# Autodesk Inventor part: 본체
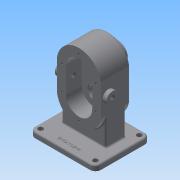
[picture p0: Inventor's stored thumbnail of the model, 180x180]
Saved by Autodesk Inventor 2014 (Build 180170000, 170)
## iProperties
Created: 2020-09
Part Number: 본체
Material: 일반
Document SubType Name: Modeling
Designer: NET
Density: 1 g/cm^3
Appearance: 기본값
Author: NET
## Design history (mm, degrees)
sketch "스케치1"
  geometry: L1 (40, 0)-(-40, 0); L2 (40, 0)-(40, 29.174); L3 (-40, 29.174)-(-40, 0); L4 (-40, -29.174)-(-40, 0); L5 (40, 0)-(40, -29.174); A1 r 40.638 centre (0, 22) between (40, 29.174) and (-40, 29.174); A2 r 40.638 centre (0, -22) between (-40, -29.174) and (40, -29.174); 2 further points
  constraints: 10 end point, 4 point on circle, 3 symmetric about line, 2 centre point, 1 coincident, 1 horizontal, 1 midpoint, 1 parallel, 1 perpendicular, 1 other
  dimensions: "d0" = 80 distance of L1.start L1.end; "d104" = 44 distance of A2.centre A1.centre
extrude "돌출1" new body sketch "스케치1" distance "d1" = 53; taper "d2" = 0 deg
node "작업 평면1"
sketch "스케치2"
  geometry: L1 (40, 53)-(-40, 53) reference; L2 (-40, 0)-(-40, 53) reference; L3 (40, 0)-(-40, 0) reference; L4 (40, -30)-(-40, -30); L5 (-40, 70)-(40, 70); L6 (40, 70)-(40, 70); L7 (-40, 26.5)-(40, 26.5); L8 (-40, 70)-(-60, 70); L9 (-60, 70)-(-60, -30); L10 (-60, -30)-(-40, -30); L11 (40, 70)-(60, 70); L12 (60, 70)-(60, -30); L13 (60, -30)-(40, -30); 2 further points
  constraints: 21 end point, 4 parallel, 2 perpendicular, 1 point on line
extrude "돌출2" join sketch "스케치2" distance "d8" = 10; taper "d9" = 0 deg
sketch "스케치3"
  geometry: L1 (-40, 70)-(-40, -30) reference; L2 (40, -30)-(40, 70) reference; L3 (60, 70)-(-60, 70) reference; L4 (-40, 45)-(40, 45); L5 (40, 45)-(40, 8); L6 (40, 8)-(-40, 8); L7 (-40, 8)-(-40, 45); 1 further point
  constraints: 8 end point, 2 parallel, 2 point on line, 1 horizontal, 1 perpendicular
  dimensions: "d10" = 25 distance between parallel lines of L4 L3; "d11" = 37 distance between parallel lines of L6 L4
extrude "돌출3" join sketch "스케치3" stored distance "d12" = 10; taper "d13" = 0 deg
sketch "스케치4"
  geometry: L1 (-24, 22)-(-24, -22); L2 (24, -22)-(24, 22); A1 r 40.638 centre (0, -22) between (-40, -29.174) and (40, -29.174) reference; A2 r 40.638 centre (0, 22) between (40, 29.174) and (-40, 29.174) reference; A3 r 24 centre (0, 22) between (24, 22) and (-24, 22); A4 r 24 centre (0, -22) between (-24, -22) and (24, -22); 1 further point
  constraints: 4 end point, 4 point on circle, 3 tangent, 2 centre point, 2 coincident
  dimensions: "d14" = 48 diameter of A3; "d15" = 48 diameter of A4
extrude "돌출4" cut sketch "스케치4" distance "d16" = 29; taper "d17" = 0 deg
sketch "스케치5"
  geometry: C1 r 12.5 at (0, 22); C2 r 12.5 at (0, -22); A1 r 24 centre (0, 22) between (24, 22) and (-24, 22) reference; A2 r 24 centre (0, -22) between (-24, -22) and (24, -22) reference; 1 further point
  constraints: 2 centre point, 2 coincident
  dimensions: "d18" = 25 diameter of C1; "d19" = 25 diameter of C2
extrude "돌출5" cut sketch "스케치5" distance "d20" = 15; taper "d21" = 0 deg
sketch "스케치6"
  geometry: C1 r 19 at (0, -22); A1 r 40.638 centre (0, -22) between (-40, -29.174) and (40, -29.174) reference; 1 further point
  constraints: 1 centre point, 1 coincident
  dimensions: "d22" = 38 diameter of C1
extrude "돌출6" join sketch "스케치6" distance "d23" = 17; taper "d24" = 0 deg
sketch "스케치7"
  geometry: C1 r 19 at (0, 0) reference; C2 r 14 at (0, 0); 1 further point
  constraints: 1 centre point, 1 coincident
  dimensions: "d25" = 28 diameter of C2
extrude "돌출7" cut sketch "스케치7" distance "d26" = 7.3; taper "d27" = 0 deg
sketch "스케치8"
  geometry: C1 r 14 at (0, 0) reference; C2 r 8.5 at (0, 0); 1 further point
  constraints: 1 centre point, 1 coincident
  dimensions: "d28" = 17 diameter of C2
extrude "돌출8" cut sketch "스케치8" stored distance "d29" = 7.3; taper "d30" = 0 deg
chamfer "모따기1" distance "d31" = 1; stored, may be unused: second distance "d32" = 2, angle "d33" = 45 deg
sketch "스케치10"
  geometry: L1 (45, -62.638)-(45, -80) reference; L2 (45, -80)-(70, -80) reference; L3 (70, -80)-(70, -90) reference; L4 (70, -90)-(-30, -90) reference; L5 (-30, -90)-(-30, -80) reference; L6 (-30, -80)-(8, -80) reference; L7 (8, -80)-(8, -62.638) reference; L8 (8, -62.638)-(0, -62.638) reference; L9 (0, -62.638)-(0, -46) reference; L10 (0, -46)-(29, -46) reference; L11 (29, -46)-(29, -35.5) reference; L12 (29, -35.5)-(30, -34.5) reference; L13 (30, -34.5)-(44, -34.5) reference; L14 (44, -34.5)-(44, -9.5) reference; L15 (44, -9.5)-(30, -9.5) reference; L16 (30, -9.5)-(29, -8.5) reference; L17 (29, -8.5)-(29, 8.5) reference; L18 (29, 8.5)-(30, 9.5) reference; L19 (30, 9.5)-(44, 9.5) reference; L20 (44, 9.5)-(44, 13.5) reference; L21 (44, 13.5)-(62.7, 13.5) reference; L22 (62.7, 13.5)-(62.7, 8) reference; L23 (62.7, 8)-(70, 8) reference; L24 (70, 8)-(70, 3) reference; L25 (70, 3)-(53, 3) reference; L26 (53, 3)-(53, -62.638) reference; L27 (53, -62.638)-(45, -62.638) reference; L28 (0, 62.638)-(53, 62.638) reference; L29 (53, 62.638)-(53, 41) reference; L30 (53, 41)-(70, 41) reference; L31 (70, 41)-(70, 36) reference; L32 (70, 36)-(62.7, 36) reference; L33 (62.7, 36)-(62.7, 30.5) reference; L34 (62.7, 30.5)-(44, 30.5) reference; L35 (44, 30.5)-(44, 34.5) reference; L36 (44, 34.5)-(30, 34.5) reference; L37 (30, 34.5)-(29, 35.5) reference; L38 (29, 35.5)-(29, 46) reference; L39 (29, 46)-(0, 46) reference; L40 (0, 46)-(0, 62.638) reference; L41 (69.3, 36)-(70, 36.404); 1 further point
  constraints: 2 end point, 2 point on line
  dimensions: "d34" = 30 deg angle of L32 L41; "d35" = 0.7 distance from line of L31 L41.start
  node "절단 모서리 투영1"
fillet "모깎기1" dims "d36" = 0.5
sketch "스케치14"
  geometry: L1 (-31, 22)-(31, -22); L2 (31, 22)-(-31, -22); 5 further points
  constraints: 4 coincident, 4 end point, 2 midpoint
hole "구멍2" sketch "스케치14" diameter "d56" = 4.134; stored, may be unused: countersink angle "d60" = 90 deg, drill point angle "d62" = 118 deg; dims "d57" = 10, "d58" = 4, "d59" = 2, "d61" = 12
sketch "스케치16"
  geometry: L1 (0, 0)-(58.348, 0) reference; L2 (119.174, -20)-(119.174, 60) reference; C1 r 11 at (29.174, 14); 2 further points
  constraints: 1 centre point, 1 coincident
  dimensions: "d70" = 90 distance from line of L2 point (29.174, 14); "d71" = 14 distance from line of L1 point (29.174, 14); "d72" = 22 diameter of C1
extrude "돌출11" join sketch "스케치16" distance "d73" = 7.1; taper "d74" = 0 deg
sketch "스케치17"
  geometry: C1 r 11 at (0, 0) reference; 2 further points
  constraints: 1 coincident
hole "구멍4" sketch "스케치17" at (0, 0) diameter "d75" = 8.376; stored, may be unused: countersink angle "d79" = 90 deg, drill point angle "d81" = 118 deg; dims "d76" = 10, "d77" = 4, "d78" = 2, "d80" = 30
fillet "모깎기3" dims "d85" = 10
sketch "스케치18"
  geometry: C1 r 4.5 at (50, -20); C2 r 4.5 at (50, 60); C3 r 4.5 at (-50, 60); C4 r 4.5 at (-50, -20); A1 r 10 centre (-50, 60) between (-50, 70) and (-60, 60) reference; A2 r 10 centre (-50, -20) between (-60, -20) and (-50, -30) reference; A3 r 10 centre (50, -20) between (50, -30) and (60, -20) reference; A4 r 10 centre (50, 60) between (60, 60) and (50, 70) reference; 1 further point
  constraints: 4 centre point, 4 coincident
  dimensions: "d87" = 9 diameter of C1; "d88" = 9 diameter of C2; "d89" = 9 diameter of C3; "d90" = 9 diameter of C4
extrude "돌출12" cut sketch "스케치18" stored distance "d91" = 7.1; taper "d92" = 0 deg
node "작업 평면2"
sketch "스케치19"
  geometry: L1 (50, -30)-(-50, -30) reference; L2 (60, -20)-(60, 60) reference; 2 further points
  constraints: 1 other
  dimensions: "d94" = 12 distance from line of L1 point (0, -18); "d95" = 60 distance from line of L2 point (0, -18)
feature "엠보싱1" sketch "스케치19" dims "d96" = 0.5, "d97" = 0
sketch "스케치20"
  geometry: L1 (70, 36)-(62.7, 36) reference; L2 (62.7, 8)-(70, 8) reference; L3 (69.324, 36)-(69.324, 8); L4 (69.324, 8)-(70.411, 7.372); 1 further point
  constraints: 4 end point, 2 point on line, 1 perpendicular
  dimensions: "d98" = 30 deg angle of L2 L4
chamfer "모따기2" distance "d99" = 0.7; stored, may be unused: second distance "d100" = 2, angle "d101" = 30 deg
fillet "모깎기4" dims "d102" = 3
fillet "모깎기5" dims "d103" = 3
sketch "스케치21"
  geometry: A1 r 24 centre (0, 22) between (24, 22) and (-24, 22) reference; 2 further points
  dimensions: "d105" = 31 distance of point (0, 53) A1.centre
hole "구멍5" sketch "스케치21" at (0, 53) diameter "d106" = 4.134; stored, may be unused: countersink angle "d110" = 90 deg, drill point angle "d112" = 118 deg; dims "d107" = 10, "d108" = 4, "d109" = 2, "d111" = 12
node "솔리드1"
mirror "대칭2"
mirror "대칭3"
